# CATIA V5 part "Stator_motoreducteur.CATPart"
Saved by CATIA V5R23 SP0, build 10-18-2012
Part number: Stator_motoreducteur
Bounding box of the stored display mesh (mm): x -32.5 to 32.5, y -47.5 to 20.956, z -2.5 to 120
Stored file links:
  P:\CORRECTION CAO\Stator_motoreducteur.CATPart
  d:\catia_soft\intel_a\reffiles\standard\MetricThickPitch.txt
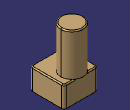
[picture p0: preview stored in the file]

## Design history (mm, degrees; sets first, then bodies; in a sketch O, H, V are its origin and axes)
Body1 "Stator" (main body)
  Sketch1 on xy-plane, origin (0, 0, 0), H (1, 0, 0), V (0, 1, 0)
    line L1 (-32.5, 17.5) -> (32.5, 17.5)
    line L2 (32.5, 17.5) -> (32.5, -47.5)
    line L3 (32.5, -47.5) -> (-32.5, -47.5)
    line L4 (-32.5, -47.5) -> (-32.5, 17.5)
    reference intersected line E1 through (0, 0) direction (0, 1) from yz-plane
    reference intersected line E2 through (0, 0) direction (-1, 0) from zx-plane
    distance L2 L4 = 65
    distance L1 L3 = 65
    distance E2 L1 = 17.5
    horizontal: L1 H, L3 H
    vertical: L2 V, L4 V
    symmetry: L2 L4 E1
  Pad1: profile Sketch1, direction (0, 0, 1), length 40
  Sketch2 on face of Pad1, origin (0, 0, 40), H (1, 0, 0), V (0, 1, 0)
    circle A1 centre (0, 0) radius 21
    radius A1 = 21
  Pad2: profile Sketch2, direction (0, 0, 1), length 80
  Fillet1: radius 4.5, on edge [face of Pad1 | face of Pad1] (x4)
  Fillet2: radius 2, on edge [face of Pad1 | face of Pad1]; edge [face of Pad2 | face of Pad2]
  Sketch3 on face of Pad1, origin (-23.3647, 9.1132, 0), H (1, 0, 0), V (0, -1, 0)
    point P1 (-4.6353, -3.8868)
    reference intersected line E1 through (23.3647, 0) direction (0, 1) from yz-plane
    reference intersected line E2 through (0, 9.1132) direction (1, 0) from zx-plane
    distance P1 E1 = 28
    distance P1 E2 = 13
  Hole1: placed by Sketch3, at (-28, 13, 0) direction (0, 0, 1), diameter 3.242, depth 15, V-bottom angle 120, threaded "M4", thread diameter 4, thread depth 12, pitch 0.7
  RectPattern1: of Hole1, direction 1 instances 2, spacing 56, along edge [face of Pad1 | face of Pad1] reversed, direction 2 instances 2, spacing 56, along edge [face of Pad1 | face of Pad1]
  Sketch4 "Esquisse.4" on face of Pad1, origin (0, 0, 0), H (1, 0, 0), V (0, -1, 0)
    circle A1 centre (0, 0) radius 7
    circle A2 centre (0, 0) radius 5
    radius A1 = 7
    radius A2 = 5
  Pad3: profile Sketch4, direction (0, 0, -1), length 2.5
  Sketch5 on start face of Pad1, origin (-0.8173, -1.8223, 0), H (1, 0, 0), V (0, -1, 0)
    point P1 (0.8173, -1.8223)
    reference projected circle E1 centre (0.8173, -1.8223) radius 5 from edge [end face of Pad3 | face of Pad3 from Sketch4.A2]
    concentricity: E1 P1
  Hole2: placed by Sketch5, at (0, 0, 0) direction (0, 0, 1), diameter 10, depth 40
